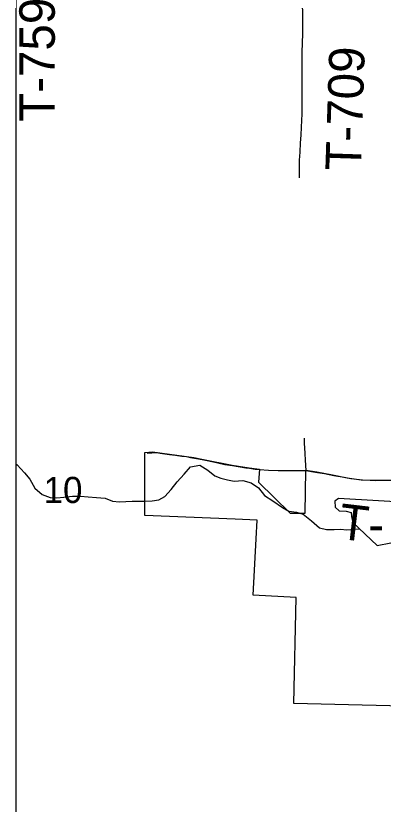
# Model space of a CAD drawing. Extents: x -7.5 to 53.5, y 0 to 22.
# Drawn here: x 2.1 to 2.688, y 15.27 to 16.532 of the extents above; entities that cross this region are included whole.
import ezdxf

# ---------------------------------------------------------------- set-up
doc = ezdxf.new("R2010")
doc.units = 0
for name, color, linetype in [('GM_X_Corporation', 7, 'Continuous'), ('GM_X_Minor_Lake', 7, 'Continuous'), ('GM_X_Minor_River', 7, 'Continuous'), ('GM_X_Section_Text', 7, 'Continuous'), ('GM_X_Township_Road', 7, 'Continuous'), ('GM_X_Township_Road_Text', 7, 'Continuous'), ('SH_Data', 7, 'Continuous')]:
    doc.layers.add(name, color=color, linetype=linetype)

msp = doc.modelspace()

# ---------------------------------------------------------------- linework, layer by layer
at = {"layer": 'GM_X_Corporation'}
for points in [[(4.6087, 14.5302), (4.6021, 15.6139), (4.594, 15.8096), (4.5873, 16.3533), (4.5872, 16.3635), (4.5826, 16.8462), (4.5822, 16.8992), (4.577, 17.1178), (4.5749, 17.2575), (4.5771, 17.6201), (4.5718, 18.1276), (4.5696, 18.2604), (4.5565, 19.1354), (5.0411, 19.1401), (6.0424, 19.1527), (6.0433, 19.1527), (6.5522, 19.1561), (7.544, 19.1455), (8.414, 19.1709), (8.5159, 19.1718), (8.9, 19.1887), (8.9, 20.9), (2.1, 20.9), (2.1, 14.1)], [(2.7865, 15.4257), (2.5449, 15.4317), (2.5491, 15.6011), (2.48, 15.6048), (2.4849, 15.6951), (2.4866, 15.725), (2.4511, 15.7264), (2.3067, 15.7323), (2.3064, 15.8335), (2.319, 15.8341), (2.385, 15.8251), (2.4007, 15.8223), (2.4466, 15.8128), (2.4738, 15.8086), (2.4901, 15.8066), (2.4885, 15.7855), (2.5392, 15.7359), (2.5635, 15.7359), (2.5645, 15.8048), (2.5817, 15.8021), (2.6068, 15.7975), (2.6306, 15.7928), (2.6527, 15.7897), (2.6671, 15.7892), (2.713, 15.7891)]]:
    msp.add_lwpolyline(points, dxfattribs=at)
at = {"layer": 'GM_X_Minor_Lake'}
for points in [[(2.6785, 15.6843), (2.7005, 15.6889), (2.7187, 15.6877), (2.7422, 15.6855), (2.7577, 15.6893), (2.7695, 15.7007), (2.7714, 15.7155), (2.7638, 15.7272), (2.7554, 15.7367), (2.7444, 15.7519), (2.6167, 15.7596), (2.6106, 15.7551), (2.6114, 15.746), (2.6174, 15.7399), (2.6288, 15.7396), (2.6371, 15.7373), (2.6372, 15.7308), (2.6398, 15.7214)], [(2.6398, 15.7214), (2.6785, 15.6843)]]:
    msp.add_lwpolyline(points, dxfattribs=at)
at = {"layer": 'GM_X_Minor_River'}
for points in [[(2.1, 15.815), (2.1022, 15.8135), (2.114, 15.8006), (2.1223, 15.7904), (2.1303, 15.7764), (2.142, 15.7662), (2.1553, 15.7612), (2.1659, 15.7609), (2.1769, 15.762), (2.1909, 15.7636), (2.2038, 15.7636), (2.216, 15.7625), (2.2292, 15.7614), (2.2429, 15.7599), (2.2546, 15.7553), (2.266, 15.7542), (2.2762, 15.7546), (2.2861, 15.7554), (2.3066, 15.7554), (2.3183, 15.7558), (2.3289, 15.7573), (2.3388, 15.7627), (2.349, 15.774), (2.3585, 15.7862), (2.3698, 15.7987), (2.3797, 15.8101), (2.3945, 15.8132), (2.4074, 15.8052), (2.4184, 15.7957), (2.4282, 15.7923), (2.4388, 15.7893), (2.4494, 15.7875), (2.4635, 15.7882), (2.4767, 15.7848), (2.4885, 15.7765), (2.4984, 15.7644), (2.5117, 15.7561), (2.5272, 15.7451), (2.5371, 15.7394), (2.5496, 15.7375)], [(2.5496, 15.7375), (2.5598, 15.7345), (2.5735, 15.7239), (2.5864, 15.7126), (2.5974, 15.7099), (2.6095, 15.71), (2.6201, 15.7103), (2.6296, 15.7096), (2.6503, 15.7113)]]:
    msp.add_lwpolyline(points, dxfattribs=at)
at = {"layer": 'GM_X_Township_Road'}
for points in [[(2.5593, 16.4987), (2.5595, 16.5091), (2.5593, 16.5308), (2.559, 16.5557), (2.5589, 16.5775), (2.5592, 16.6024), (2.5596, 16.6304), (2.5599, 16.6553), (2.5609, 16.7051), (2.5613, 16.7237), (2.5616, 16.7362), (2.562, 16.7547), (2.5626, 16.7733), (2.5632, 16.7888), (2.5638, 16.8043), (2.5642, 16.823), (2.5644, 16.8386), (2.5648, 16.8603), (2.5652, 16.8727), (2.5657, 16.8851), (2.5666, 16.9029)], [(2.555, 16.3139), (2.5559, 16.3289), (2.5567, 16.3413), (2.5574, 16.3537), (2.5583, 16.3755), (2.5587, 16.3972), (2.5587, 16.4159), (2.5587, 16.4315), (2.5586, 16.4439), (2.5585, 16.4688), (2.5592, 16.4936), (2.5593, 16.4987)], [(2.5544, 16.273), (2.554, 16.2885), (2.5541, 16.301), (2.555, 16.3139)], [(2.5647, 15.8042), (2.5637, 15.821), (2.5631, 15.8319), (2.5629, 15.8408), (2.5623, 15.8477), (2.5621, 15.8564)], [(2.3101, 15.8324), (2.3252, 15.8331), (2.3312, 15.8324), (2.3463, 15.8302), (2.3555, 15.8289), (2.3656, 15.8275), (2.3734, 15.8266), (2.3799, 15.8253), (2.3893, 15.8239), (2.4013, 15.8215), (2.4164, 15.8183), (2.4346, 15.8143), (2.4468, 15.8122), (2.4559, 15.8107), (2.4681, 15.8088), (2.474, 15.808), (2.4832, 15.8068), (2.4904, 15.8061)], [(2.4904, 15.8061), (2.5047, 15.8051), (2.5202, 15.8046), (2.5449, 15.8043), (2.5647, 15.8042)], [(2.5647, 15.8042), (2.5732, 15.803), (2.5831, 15.8013), (2.5941, 15.7996), (2.6089, 15.7967), (2.6259, 15.7936), (2.6362, 15.7916), (2.6455, 15.7905), (2.6548, 15.7897), (2.6671, 15.7888), (2.6761, 15.7884), (2.6823, 15.7887), (2.6887, 15.7887)]]:
    msp.add_lwpolyline(points, dxfattribs=at)
at = {"layer": 'SH_Data'}
msp.add_line((2.1, 20.9), (2.1, 14.1), dxfattribs=at)

# ---------------------------------------------------------------- texts
at = {"layer": 'GM_X_Section_Text'}
msp.add_text('10', height=0.04186, rotation=0, dxfattribs=at).set_placement((2.1445, 15.7524))
at = {"layer": 'GM_X_Township_Road_Text'}
for s, height, rotation, p in [('T-759', 0.05682, 90, (2.1625, 16.3626)), ('T-709', 0.05682, 88.1185, (2.6523, 16.2836)), ('T', 0.0568, 353.2774, (2.615, 15.6954)), ('-', 0.0568, 359.5082, (2.664, 15.69))]:
    msp.add_text(s, height=height, rotation=rotation, dxfattribs=at).set_placement(p)

doc.saveas('drawing.dxf')
